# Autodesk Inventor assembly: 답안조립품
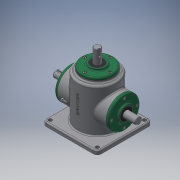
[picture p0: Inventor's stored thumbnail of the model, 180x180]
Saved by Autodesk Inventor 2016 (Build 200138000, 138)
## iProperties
Created: 2019-08
Part Number: 답안조립품
Material: 일반
Document SubType Name: Assembly
Designer: user
Author: user
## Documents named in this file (16)
- D:\490823V1011\답안조립품.iam
- D:\490823V1011\메인 베벨기어.ipt
- D:\490823V1011\메인 축.ipt
- 메인 축.ipt
- D:\490823V1011\베어링 6203.ipt
- D:\490823V1011\본체.ipt
- D:\490823V1011\볼트 M4.ipt
- 볼트 M4.ipt
- D:\490823V1011\서브 베벨기어.ipt
- D:\490823V1011\서브 축.ipt
- 서브 축.ipt
- D:\490823V1011\오일 실.ipt
- 오일 실.ipt
- D:\490823V1011\커버.ipt
- D:\490823V1011\키 4x4.ipt
- D:\490823V1011\키 5x5.ipt
